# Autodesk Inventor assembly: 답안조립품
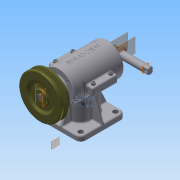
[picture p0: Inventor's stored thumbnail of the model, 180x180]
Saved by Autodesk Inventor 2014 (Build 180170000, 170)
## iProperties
Created: 2015-05
Part Number: 답안조립품
Document SubType Name: Assembly
Designer: net
Mass: 1936.9 g
Surface Area: 1472.73 cm^2
Volume: 476.409 cm^3
Density: 4.06562 g/cm^3
Author: net
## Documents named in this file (18)
- C:\Users\net\Desktop\350507V1037\답안조립품.iam
- C:\Users\net\Desktop\350507V1037\본체.ipt
- C:\Users\net\Desktop\350507V1037\본체 커버.ipt
- C:\Users\net\Desktop\350507V1037\뒤커버.ipt
- C:\Users\net\Desktop\350507V1037\베어링 6202.ipt
- C:\Users\net\Desktop\350507V1037\앞커버.ipt
- C:\Users\net\Desktop\350507V1037\베어링 6201.ipt
- C:\Users\net\Desktop\350507V1037\오일실.ipt
- C:\Users\net\Desktop\350507V1037\편심축.ipt
- C:\Users\net\Desktop\350507V1037\키4x4.ipt
- C:\Users\net\Desktop\350507V1037\V-벨트풀리.ipt
- C:\Users\net\Desktop\350507V1037\멈춤나사.ipt
- C:\Users\net\Desktop\350507V1037\링크.ipt
- C:\Users\net\Desktop\350507V1037\너트 M8.ipt
- C:\Users\net\Desktop\350507V1037\M4x0.5x14.ipt
- C:\Users\net\Desktop\350507V1037\M3x0.5x8.ipt
- C:\Users\net\Desktop\350507V1037\슬라이드.ipt
- C:\Users\net\Desktop\350507V1037\가변스프링.ipt
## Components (15 placed, 5 different names)
1. V-벨트풀리:1 — 각도:2
2. KS B 1012 C - 미터 C M8:1
3. M4x0.5x14:1
4. M4x0.5x14:2
5. M4x0.5x14:3
6. M4x0.5x14:4
7. M3x0.5x8:1
8. M3x0.5x8:2
9. M3x0.5x8:3
10. M3x0.5x8:4
11. M3x0.5x8:5
12. M3x0.5x8:6
13. M3x0.5x8:7
14. M3x0.5x8:8
15. 가변스프링:1
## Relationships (1: Angle 1)
- 각도:2 [Angle]: V-벨트풀리:1
